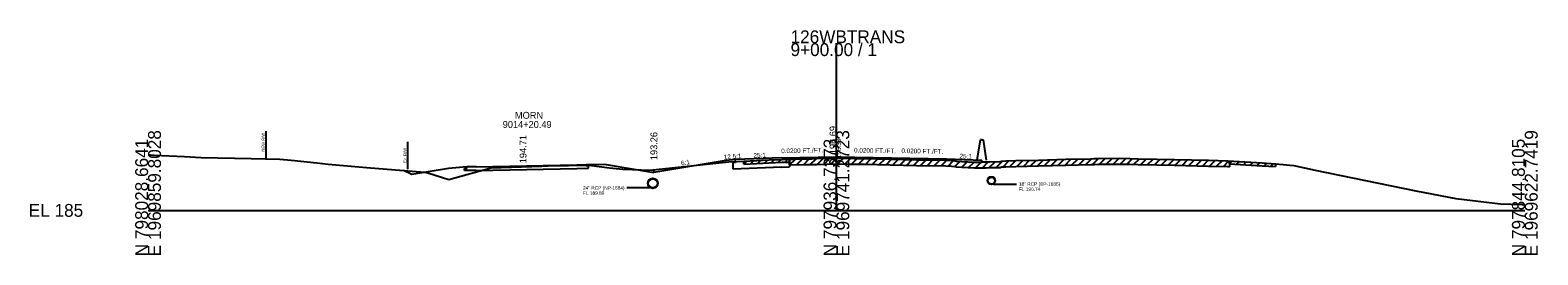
# Model space of a CAD drawing. Extents: x -6494 to 1970605, y -10 to 798140.
# Drawn here: x -25.7 to 302.8, y 1490.3 to 1539.3 of the extents above; entities that cross this region are included whole.
import ezdxf

# ---------------------------------------------------------------- set-up
doc = ezdxf.new("R2010")
doc.units = 0
for name, color, linetype in [('RD_GPK_XS_Cell', 7, 'Continuous'), ('RD_XS_Base', 7, 'Continuous'), ('RD_XS_EarthShd', 7, 'Continuous'), ('RD_XS_ExGround', 7, 'Continuous'), ('RD_XS_ExPaveRet', 7, 'Continuous'), ('RD_XS_ExRW', 7, 'Continuous'), ('RD_XS_MedBWall', 7, 'Continuous'), ('RD_XS_Misc_Line', 7, 'Continuous'), ('RD_XS_NewRW', 7, 'Continuous'), ('RD_XS_Pave', 7, 'Continuous'), ('RD_XS_PaveOvlay', 7, 'Continuous'), ('RD_XS_PaveShd', 7, 'Continuous'), ('RD_XS_Pipe', 7, 'Continuous'), ('RD_XS_TieSlope', 7, 'Continuous'), ('RD_XS_TX_Elev_EX', 7, 'Continuous'), ('RD_XS_TX_Elev_PR', 7, 'Continuous'), ('RD_XS_TX_Misc', 7, 'Continuous'), ('RD_XS_TX_Profile', 7, 'Continuous'), ('RD_XS_TX_ShdSlope', 7, 'Continuous'), ('RD_XS_TX_Slope', 7, 'Continuous'), ('RD_XS_TX_Station', 7, 'Continuous')]:
    doc.layers.add(name, color=color, linetype=linetype)

msp = doc.modelspace()

# ---------------------------------------------------------------- linework, layer by layer
at = {"layer": 'RD_GPK_XS_Cell'}
for p, q in [((150, 1500), (150, 1536.42)), ((0, 1500), (150, 1500)), ((150, 1500), (300, 1500))]:
    msp.add_line(p, q, dxfattribs=at)
at = {"layer": 'RD_XS_Base'}
for p, q in [((68.96, 1509.14), (69.46, 1509.15)), ((68.96, 1508.66), (68.96, 1509.14)), ((71.46, 1508.71), (68.96, 1508.66)), ((69.46, 1509.15), (69.46, 1509.45)), ((93.46, 1509.15), (95.96, 1509.21)), ((95.46, 1509.67), (95.46, 1509.97)), ((95.96, 1509.69), (95.46, 1509.67)), ((95.96, 1509.21), (95.96, 1509.69)), ((127.5, 1510.47), (128, 1510.49)), ((127.5, 1508.99), (127.5, 1510.47)), ((138, 1509.41), (127.5, 1508.99)), ((128, 1510.49), (128, 1511.05)), ((138, 1509.41), (139.8, 1509.45))]:
    msp.add_line(p, q, dxfattribs=at)
at = {"layer": 'RD_XS_EarthShd'}
for p, q in [((69.46, 1509.45), (65.46, 1509.13)), ((95.46, 1509.97), (99.46, 1510.06)), ((128, 1511.05), (126, 1510.89))]:
    msp.add_line(p, q, dxfattribs=at)
at = {"layer": 'RD_XS_ExGround'}
msp.add_lwpolyline([(0, 1512.14), (1.05, 1512.05), (1.35, 1512.02), (7.97, 1511.71), (11.58, 1511.52), (22.44, 1511.32), (28.72, 1511.19), (31.18, 1510.96), (36.75, 1510.34), (39.24, 1510.07), (44.25, 1509.65), (47.62, 1509.33), (60.24, 1508.35), (60.95, 1508.19), (65.57, 1506.76), (69.43, 1507.82), (74.77, 1509.29), (85.79, 1509.66), (86.46, 1509.69), (87.18, 1509.7), (96.04, 1509.83), (100.58, 1509.29), (103.49, 1508.97), (105.54, 1508.88), (109.35, 1508.76), (120.3, 1509.91), (126.51, 1510.56), (128.35, 1510.65), (129.8, 1510.7), (135.34, 1510.98), (138.14, 1511.11), (143.57, 1511.22), (144.62, 1511.24), (145.75, 1511.27), (150.02, 1511.38), (152.77, 1511.34), (153.85, 1511.32), (156.11, 1511.28), (161.7, 1511.17), (167.43, 1511.04), (173.77, 1510.92), (175.05, 1510.85), (175.8, 1510.82), (176.11, 1510.71), (177.35, 1510.64), (179.99, 1510.51), (181.85, 1510.54), (182.66, 1510.54), (183.37, 1510.56), (185.71, 1510.62), (185.98, 1510.73), (186.9, 1510.76), (189.07, 1510.84), (194.02, 1510.97), (199.95, 1511.13), (205.36, 1511.25), (206.18, 1511.27), (207.13, 1511.28), (211.78, 1511.35), (213.9, 1511.3), (215.75, 1511.26), (219.78, 1511.18), (223.7, 1511.1), (231.1, 1510.9), (235.28, 1510.78), (242.79, 1510.33), (245.67, 1510.17), (247.35, 1510), (248.82, 1509.84), (249.69, 1509.76), (254.3, 1508.78), (276.24, 1504.25), (284.94, 1502.57), (294.73, 1501.44), (299.41, 1501.27), (300, 1501.26)], dxfattribs=at)
at = {"layer": 'RD_XS_ExPaveRet'}
for p, q in [((129.8, 1510.08), (129.8, 1510.7)), ((129.8, 1510.08), (135.34, 1510.35)), ((135.34, 1510.35), (138.14, 1510.49)), ((138.14, 1510.49), (139.8, 1510.52)), ((139.8, 1509.9), (139.8, 1511.15)), ((139.8, 1511.15), (139.8, 1510.52)), ((139.8, 1509.9), (143.57, 1509.97)), ((143.57, 1509.97), (144.62, 1509.99)), ((144.62, 1509.99), (145.75, 1510.02)), ((145.75, 1510.02), (150.02, 1510.13)), ((150.02, 1510.13), (152.77, 1510.09)), ((152.77, 1510.09), (153.85, 1510.07)), ((153.85, 1510.07), (156.11, 1510.03)), ((156.11, 1510.03), (161.7, 1509.92)), ((161.7, 1509.92), (167.43, 1509.79)), ((167.43, 1509.79), (173.77, 1509.67)), ((173.77, 1509.67), (175.05, 1509.6)), ((175.05, 1509.6), (175.8, 1509.57)), ((175.8, 1509.57), (176.11, 1509.46)), ((176.11, 1509.46), (177.35, 1509.39)), ((177.35, 1509.39), (179.99, 1509.26)), ((179.99, 1509.26), (181.85, 1509.29)), ((181.85, 1509.29), (182.66, 1509.29)), ((182.66, 1509.29), (183.37, 1509.31)), ((183.37, 1509.31), (185.71, 1509.37)), ((185.71, 1509.37), (185.98, 1509.48)), ((185.98, 1509.48), (186.9, 1509.51)), ((186.9, 1509.51), (189.07, 1509.59)), ((189.07, 1509.59), (194.02, 1509.72)), ((194.02, 1509.72), (199.95, 1509.88)), ((199.95, 1509.88), (205.36, 1510)), ((205.36, 1510), (206.18, 1510.02)), ((206.18, 1510.02), (207.13, 1510.03)), ((207.13, 1510.03), (211.78, 1510.1)), ((211.78, 1510.1), (213.9, 1510.05)), ((213.9, 1510.05), (215.75, 1510.01)), ((215.75, 1510.01), (219.78, 1509.93)), ((219.78, 1509.93), (223.7, 1509.85)), ((223.7, 1509.85), (231.1, 1509.65)), ((231.1, 1509.65), (235.28, 1509.53)), ((235.28, 1509.53), (235.67, 1509.51)), ((235.67, 1510.76), (235.67, 1509.51)), ((235.67, 1510.13), (235.67, 1510.76)), ((235.67, 1510.13), (242.79, 1509.71)), ((242.79, 1509.71), (245.67, 1509.54)), ((245.67, 1510.17), (245.67, 1509.54))]:
    msp.add_line(p, q, dxfattribs=at)
at = {"layer": 'RD_XS_ExRW'}
msp.add_line((56.56, 1514.95), (56.56, 1508.95), dxfattribs=at)
at = {"layer": 'RD_XS_MedBWall'}
for p, q in [((180.7, 1510.92), (181.36, 1515.4)), ((181.7, 1515.4), (181.36, 1515.4)), ((181.7, 1515.4), (182.03, 1515.4)), ((182.7, 1510.92), (182.03, 1515.4))]:
    msp.add_line(p, q, dxfattribs=at)
at = {"layer": 'RD_XS_Misc_Line'}
for p, q in [((144.3, 1509.98), (145.59, 1511.26)), ((145.8, 1510.02), (147.09, 1511.3)), ((147.31, 1510.06), (148.59, 1511.34)), ((148.81, 1510.1), (150.09, 1511.38)), ((150.31, 1510.12), (151.54, 1511.36)), ((151.81, 1510.1), (153.04, 1511.33)), ((153.31, 1510.08), (154.53, 1511.31)), ((154.81, 1510.05), (156.03, 1511.28)), ((204.31, 1509.98), (205.59, 1511.26)), ((205.81, 1510.01), (207.08, 1511.28)), ((207.31, 1510.03), (208.58, 1511.3)), ((208.81, 1510.06), (210.08, 1511.33)), ((210.31, 1510.08), (211.58, 1511.35)), ((211.81, 1510.1), (213.03, 1511.32)), ((213.31, 1510.07), (214.53, 1511.29)), ((214.81, 1510.03), (216.03, 1511.25)), ((129.8, 1510.08), (130.46, 1510.73)), ((131.3, 1510.15), (131.96, 1510.81)), ((132.8, 1510.22), (133.46, 1510.88)), ((134.3, 1510.3), (134.96, 1510.96)), ((135.8, 1510.37), (136.46, 1511.03)), ((137.3, 1510.45), (137.96, 1511.1)), ((138.8, 1510.5), (139.44, 1511.14)), ((139.8, 1509.9), (141.08, 1511.17)), ((141.3, 1509.92), (142.58, 1511.2)), ((142.8, 1509.95), (144.08, 1511.23)), ((156.31, 1510.02), (157.53, 1511.25)), ((157.81, 1509.99), (159.03, 1511.22)), ((159.31, 1509.96), (160.53, 1511.19)), ((160.81, 1509.94), (162.03, 1511.16)), ((162.31, 1509.9), (163.53, 1511.13)), ((163.81, 1509.87), (165.03, 1511.1)), ((165.31, 1509.84), (166.53, 1511.06)), ((166.81, 1509.81), (168.03, 1511.03)), ((168.31, 1509.78), (169.53, 1511)), ((169.81, 1509.75), (171.03, 1510.98)), ((171.31, 1509.72), (172.53, 1510.95)), ((172.81, 1509.69), (174.03, 1510.91)), ((174.31, 1509.64), (175.5, 1510.83)), ((175.81, 1509.57), (176.9, 1510.66)), ((177.31, 1509.39), (178.5, 1510.58)), ((178.81, 1509.32), (180, 1510.51)), ((180.31, 1509.27), (181.57, 1510.53)), ((181.81, 1509.29), (183.07, 1510.55)), ((183.31, 1509.31), (184.59, 1510.59)), ((184.81, 1509.35), (186.2, 1510.74)), ((186.31, 1509.49), (187.6, 1510.79)), ((187.81, 1509.54), (189.1, 1510.84)), ((189.31, 1509.59), (190.59, 1510.88)), ((190.81, 1509.63), (192.09, 1510.92)), ((192.31, 1509.67), (193.59, 1510.96)), ((193.81, 1509.72), (195.09, 1511)), ((195.31, 1509.76), (196.59, 1511.04)), ((196.81, 1509.8), (198.09, 1511.08)), ((198.31, 1509.84), (199.59, 1511.12)), ((199.81, 1509.88), (201.09, 1511.16)), ((201.31, 1509.91), (202.59, 1511.19)), ((202.81, 1509.95), (204.09, 1511.22)), ((216.31, 1510), (217.54, 1511.22)), ((217.81, 1509.97), (219.04, 1511.19)), ((219.31, 1509.94), (220.54, 1511.16)), ((220.81, 1509.91), (222.04, 1511.13)), ((222.31, 1509.88), (223.54, 1511.1)), ((223.81, 1509.85), (225.03, 1511.07)), ((225.31, 1509.81), (226.53, 1511.03)), ((226.81, 1509.77), (228.03, 1510.98)), ((228.31, 1509.73), (229.53, 1510.94)), ((229.81, 1509.69), (231.03, 1510.9)), ((231.31, 1509.65), (232.53, 1510.86)), ((232.81, 1509.6), (234.03, 1510.82)), ((234.31, 1509.56), (235.52, 1510.77)), ((235.67, 1510.13), (236.26, 1510.72)), ((237.17, 1510.04), (237.76, 1510.63)), ((238.67, 1509.95), (239.26, 1510.54)), ((240.17, 1509.86), (240.76, 1510.45)), ((241.67, 1509.78), (242.26, 1510.37)), ((243.17, 1509.69), (243.76, 1510.28)), ((244.67, 1509.6), (245.26, 1510.19))]:
    msp.add_line(p, q, dxfattribs=at)
at = {"layer": 'RD_XS_NewRW'}
msp.add_line((25.69, 1517.25), (25.69, 1511.25), dxfattribs=at)
at = {"layer": 'RD_XS_Pave'}
for p, q in [((138, 1511.45), (150, 1511.69)), ((150, 1511.69), (174, 1511.21)), ((71.46, 1509.49), (82.46, 1509.71)), ((71.46, 1508.71), (82.46, 1508.93)), ((82.46, 1509.71), (93.46, 1509.93)), ((82.46, 1508.93), (93.46, 1509.15))]:
    msp.add_line(p, q, dxfattribs=at)
at = {"layer": 'RD_XS_PaveOvlay'}
for p, q in [((144.62, 1511.24), (145.75, 1511.27)), ((145.75, 1511.27), (150.02, 1511.38)), ((150.02, 1511.38), (152.77, 1511.34)), ((152.77, 1511.34), (153.85, 1511.32)), ((153.85, 1511.32), (156.11, 1511.28)), ((156.11, 1511.28), (161.7, 1511.17)), ((139.8, 1511.15), (143.57, 1511.22)), ((139.8, 1511.15), (139.8, 1509.45)), ((143.57, 1511.22), (144.62, 1511.24)), ((161.7, 1511.17), (167.43, 1511.04)), ((167.43, 1511.04), (173.77, 1510.92)), ((173.77, 1510.92), (175.05, 1510.85)), ((175.05, 1510.85), (175.8, 1510.82)), ((175.8, 1510.82), (176.11, 1510.71)), ((176.11, 1510.71), (177.35, 1510.64)), ((177.35, 1510.64), (179.99, 1510.51)), ((179.99, 1510.51), (181.7, 1510.53))]:
    msp.add_line(p, q, dxfattribs=at)
at = {"layer": 'RD_XS_PaveShd'}
for p, q in [((138, 1511.45), (128, 1511.05)), ((71.46, 1509.49), (69.46, 1509.45)), ((93.46, 1509.93), (95.46, 1509.97)), ((174, 1511.21), (181.7, 1510.9)), ((181.7, 1510.53), (181.7, 1510.9))]:
    msp.add_line(p, q, dxfattribs=at)
at = {"layer": 'RD_XS_Pipe'}
for p, q in [((109.33, 1504.89), (104.33, 1504.89)), ((184.26, 1505.74), (189.26, 1505.74))]:
    msp.add_line(p, q, dxfattribs=at)
for centre, radius in [((110, 1505.89), 1.1), ((110, 1505.89), 1), ((183.76, 1506.49), 0.85), ((183.76, 1506.49), 0.75)]:
    msp.add_circle(centre, radius, dxfattribs=at)
at = {"layer": 'RD_XS_TieSlope'}
for p, q in [((57.45, 1507.79), (55.63, 1508.7)), ((65.46, 1509.13), (57.45, 1507.79)), ((99.46, 1510.06), (110.22, 1508.26)), ((126, 1510.89), (110.22, 1508.26)), ((110.22, 1508.26), (110.22, 1508.86))]:
    msp.add_line(p, q, dxfattribs=at)

# ---------------------------------------------------------------- texts
at = {"layer": 'RD_GPK_XS_Cell'}
for s, p in [('126WBTRANS', (140, 1536.42)), ('9+00.00 / 1', (140, 1533.62)), ('EL 185', (-26, 1498.6))]:
    msp.add_text(s, height=2.8, dxfattribs=at).set_placement(p)
for s, p in [('N 798028.6641', (0, 1490)), ('E 1969859.8028', (2.8, 1490)), ('N 797936.7373', (150, 1490)), ('E 1969741.2723', (152.8, 1490)), ('N 797844.8105', (300, 1490)), ('E 1969622.7419', (302.8, 1490))]:
    msp.add_text(s, height=2.8, rotation=90, dxfattribs=at).set_placement(p)
at = {"layer": 'RD_XS_ExRW'}
msp.add_text('Ex. R/W ', height=0.65, rotation=90, dxfattribs=at).set_placement((56.31, 1510.33))
at = {"layer": 'RD_XS_NewRW'}
msp.add_text('NEW R/W ', height=0.65, rotation=90, dxfattribs=at).set_placement((25.42, 1512.81))
at = {"layer": 'RD_XS_Pipe'}
for s, p in [('24" RCP (NP-1684)', (94.77, 1504.52)), ('18" RCP (EP-1686)', (189.76, 1505.36)), ('FL 190.74', (189.76, 1504.24)), ('FL 189.89', (94.77, 1503.39))]:
    msp.add_text(s, height=0.75, dxfattribs=at).set_placement(p)
at = {"layer": 'RD_XS_TX_Elev_EX'}
msp.add_text('196.38', height=1, rotation=90, dxfattribs=at).set_placement((151, 1511.38))
at = {"layer": 'RD_XS_TX_Elev_PR'}
for s, p in [(' 196.69', (150, 1511.69)), (' 194.71', (82.46, 1509.71))]:
    msp.add_text(s, height=1.5, rotation=90, dxfattribs=at).set_placement(p)
at = {"layer": 'RD_XS_TX_Misc'}
msp.add_text('193.26', height=1.5, rotation=90, dxfattribs=at).set_placement((110.97, 1510.94))
at = {"layer": 'RD_XS_TX_Profile'}
for rotation, p in [(2.2906, (131.94, 1511.46)), (357.7094, (176.8, 1511.35))]:
    msp.add_text('25:1', height=1, rotation=rotation, dxfattribs=at).set_placement(p)
at = {"layer": 'RD_XS_TX_ShdSlope'}
msp.add_text('12.5:1', height=1, rotation=4.5739, dxfattribs=at).set_placement((125.5, 1511.1))
at = {"layer": 'RD_XS_TX_Slope'}
for s, rotation, p in [('0.0200 FT./FT.', 1.1458, (137.98, 1512.45)), ('0.0200 FT./FT.', 358.8542, (153.83, 1512.62)), ('0.0200 FT./FT.', 358.8542, (164.15, 1512.5)), ('6:1', 9.4623, (116.22, 1509.77))]:
    msp.add_text(s, height=1, rotation=rotation, dxfattribs=at).set_placement(p)
at = {"layer": 'RD_XS_TX_Station'}
for s, p in [('MORN', (79.95, 1519.96)), ('9014+20.49', (77.28, 1517.96))]:
    msp.add_text(s, height=1.5, dxfattribs=at).set_placement(p)

doc.saveas('drawing.dxf')
